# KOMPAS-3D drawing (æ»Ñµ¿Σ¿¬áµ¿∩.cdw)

Referenced files: Спецификация.cdw
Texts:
  Ролик регулируемый Спецификация
  Текст на чертеже
  Размерные надписи
  Шероховатость
  Линия-выноска #1
  Линия-выноска #2
  Линия-выноска #3
  Отклонения формы и база
  Заголовок таблицы
  Ячейка таблицы
  Стрелка вида
  Обозначение изменения
  Фигурная скобка
  Номер узла
  Марка координационной оси
  VRCB
  Выносная надпись
  Обозначение узла
  Марка/позиционное обозначение с линией-выноской
  Марка/позиционное обозначение на линии
  Марка/позиционное обозначение без линии-выноски
  Ролик регулируемый
  ХХХХ.ХХ.ХХ.00 СБ
  Документация
  Сборочный чертеж.
  Детали
  Корпус
  Стойка
  Ролик
  Клин
  Ось
  Крышка
  Винт М20
  Болт М16
  Стандартные изделия
  ГОСТ 1477-93
  Гайка М16.5 ГОСТ 5915-70
  Гайка М12.5 ГОСТ 5915-70
  Шпилька М12х25 15 18 58
Dimensions and other numbers on the sheet: 7; 4; 1:1; 1; 2; 3; 5; 6; 8; 0; 9; 10; 11; 12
